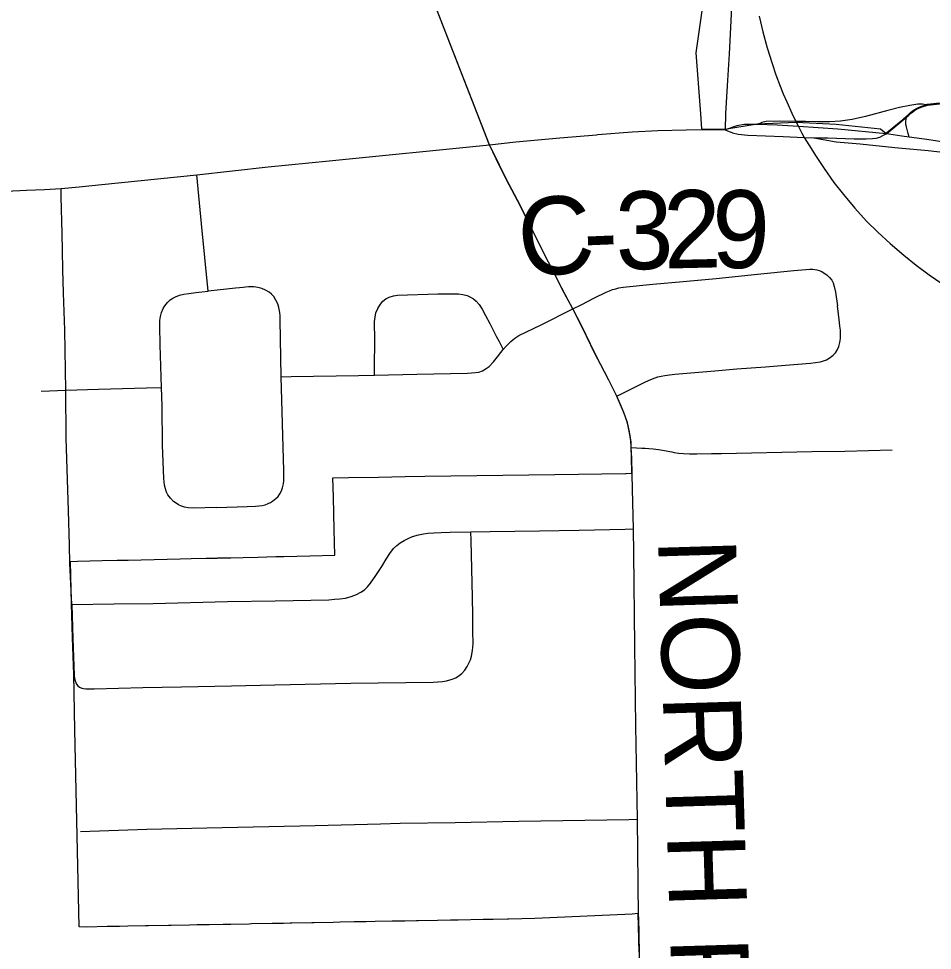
# Model space of a CAD drawing. Extents: x -6.4 to 34, y -4.2 to 22.
# Drawn here: x 3.822 to 4.489, y 17.606 to 18.286 of the extents above; entities that cross this region are included whole.
import ezdxf

# ---------------------------------------------------------------- set-up
doc = ezdxf.new("R2010")
doc.units = 0
for name, color, linetype in [('GM_X_City_Street', 7, 'Continuous'), ('GM_X_Corporation', 7, 'Continuous'), ('GM_X_County_Road', 7, 'Continuous'), ('GM_X_County_Road_Text', 7, 'Continuous'), ('GM_X_Interchange_Ramps', 7, 'Continuous'), ('GM_X_State_Route', 7, 'Continuous'), ('GM_X_Township_Road', 7, 'Continuous')]:
    doc.layers.add(name, color=color, linetype=linetype)

msp = doc.modelspace()

# ---------------------------------------------------------------- linework, layer by layer
at = {"layer": 'GM_X_City_Street'}
for points in [[(3.96669, 17.92881), (3.94956, 17.92831), (3.94597, 17.92852), (3.94309, 17.92911), (3.9409, 17.92989), (3.93872, 17.93082), (3.93703, 17.93198), (3.93517, 17.93332), (3.93286, 17.93563), (3.93114, 17.9381), (3.93008, 17.94016), (3.9293, 17.94237), (3.9285, 17.94515), (3.92824, 17.94764), (3.92798, 17.95007), (3.92719, 17.97433), (3.9268, 18.00298), (3.92636, 18.01641), (3.92534, 18.04756), (3.92515, 18.06117), (3.92525, 18.06541), (3.92571, 18.06838), (3.9265, 18.07126), (3.92766, 18.074), (3.92884, 18.07604), (3.93066, 18.07839), (3.93281, 18.08043), (3.93473, 18.08176), (3.93669, 18.08267), (3.93954, 18.08374), (3.94274, 18.08454), (3.9463, 18.08507), (3.95155, 18.08575), (3.96047, 18.0868), (3.95567, 18.13599), (3.95218, 18.1718)], [(3.86092, 17.85807), (3.8596, 17.88825), (3.85921, 17.90128), (3.85845, 17.92672), (3.85694, 17.97949), (3.85673, 18.01448), (3.85577, 18.05828), (3.85481, 18.08548), (3.85445, 18.10223), (3.85429, 18.11649), (3.85398, 18.12892), (3.85333, 18.15554), (3.85316, 18.16181)], [(3.96669, 17.92881), (3.98887, 17.9295), (3.99504, 17.92972), (3.99983, 17.93022), (4.00212, 17.9308), (4.00427, 17.93173), (4.0058, 17.93246), (4.00737, 17.93351), (4.00973, 17.93534), (4.01139, 17.93699), (4.01278, 17.93888), (4.01389, 17.94095), (4.01471, 17.94316), (4.01533, 17.94605), (4.01552, 17.94831), (4.01568, 17.95025), (4.01567, 17.95292), (4.01566, 17.95575), (4.01358, 18.02423), (4.01305, 18.0658), (4.01287, 18.06874), (4.01272, 18.07124), (4.01204, 18.07477), (4.01119, 18.07764), (4.00991, 18.08029), (4.00826, 18.08279), (4.00672, 18.08455), (4.00491, 18.08601), (4.00238, 18.08751), (3.99962, 18.08863), (3.99673, 18.08941), (3.99377, 18.08982), (3.99185, 18.09002), (3.98981, 18.08994), (3.98776, 18.08976), (3.98592, 18.08957), (3.98329, 18.08927), (3.98038, 18.08894), (3.96047, 18.0868)], [(4.08186, 18.02551), (4.08189, 18.03146), (4.08199, 18.05072), (4.08184, 18.06469), (4.08225, 18.06789), (4.08286, 18.07101), (4.08417, 18.0742), (4.08614, 18.07731), (4.08784, 18.07937), (4.0901, 18.08124), (4.09244, 18.08246), (4.09564, 18.0834), (4.09855, 18.08377), (4.12807, 18.08479), (4.13682, 18.08492), (4.14026, 18.08487), (4.14309, 18.08482), (4.14629, 18.08445), (4.14942, 18.08359), (4.1518, 18.08251), (4.15402, 18.08111), (4.156, 18.07939), (4.15812, 18.07694), (4.16021, 18.07371), (4.16273, 18.069), (4.1658, 18.06327), (4.16814, 18.05869), (4.17061, 18.05388), (4.17264, 18.04999), (4.17569, 18.04414)], [(4.01358, 18.02423), (4.02099, 18.02437), (4.07009, 18.02528), (4.08186, 18.02551), (4.11269, 18.02609), (4.14971, 18.027), (4.15541, 18.02731), (4.158, 18.02776), (4.16048, 18.02865), (4.16335, 18.03022), (4.16542, 18.03185), (4.1685, 18.0351), (4.17145, 18.03889), (4.17384, 18.04197), (4.17569, 18.04414), (4.17785, 18.04666), (4.17948, 18.04833), (4.18126, 18.05015), (4.18259, 18.05133), (4.18407, 18.05242), (4.18549, 18.05343), (4.18713, 18.05438), (4.20327, 18.06228), (4.22634, 18.07376)], [(3.83863, 18.01387), (3.85673, 18.01448), (3.88046, 18.01529), (3.91556, 18.01615), (3.92636, 18.01641)]]:
    msp.add_lwpolyline(points, dxfattribs=at)
at = {"layer": 'GM_X_Corporation'}
for points in [[(4.32282, 18.30701), (4.31607, 18.26071), (4.31952, 18.21626), (4.32042, 18.20533), (4.33727, 18.20509), (4.36096, 18.20893), (4.38948, 18.21011), (4.41864, 18.2086), (4.45099, 18.20522), (4.45476, 18.20215), (4.45682, 18.20367), (4.46706, 18.21211), (4.46957, 18.21426), (4.47124, 18.21585), (4.47248, 18.21702), (4.47415, 18.21836), (4.47549, 18.21923), (4.47702, 18.22017), (4.47859, 18.22091), (4.48032, 18.22169), (4.48506, 18.22318), (4.49382, 18.22417)], [(4.27477, 17.60429), (4.2742, 17.63243), (4.26978, 17.63193), (4.19881, 17.62872), (4.17986, 17.62838), (4.1789, 17.62836), (4.1684, 17.62818), (4.16092, 17.62805), (4.14283, 17.62772), (4.13724, 17.62762), (4.12767, 17.62744), (4.11355, 17.62717), (4.11252, 17.62715), (4.10395, 17.62699), (4.09736, 17.62686), (4.09461, 17.62681), (4.0822, 17.62657), (4.07566, 17.62644), (4.06704, 17.62628), (4.05672, 17.62608), (4.05173, 17.62599), (4.03777, 17.62572), (4.03594, 17.62568), (4.02141, 17.62541), (4.02014, 17.62538), (4.0154, 17.6253), (4.01067, 17.6252), (4.0072, 17.62513), (3.99204, 17.62484), (3.99041, 17.62481), (3.97689, 17.62455), (3.97146, 17.62445), (3.96119, 17.62425), (3.95251, 17.62409), (3.94673, 17.62398), (3.93357, 17.62373), (3.93153, 17.62369), (3.91696, 17.62341), (3.91462, 17.62337), (3.90181, 17.62315), (3.89568, 17.62304), (3.88665, 17.62288), (3.87195, 17.62261), (3.86645, 17.62276), (3.86306, 17.76652), (3.8624, 17.80712), (3.86144, 17.83361), (3.86072, 17.85862), (3.86012, 17.88933), (3.86512, 17.88964), (3.88311, 17.89006), (3.89408, 17.89031), (3.90205, 17.89049), (3.921, 17.89093), (3.93994, 17.89137), (3.94797, 17.89155), (3.95889, 17.8918), (3.96691, 17.89199), (3.96752, 17.892), (3.97699, 17.89222), (3.98585, 17.89242), (3.99677, 17.89268), (4.00991, 17.89298), (4.01572, 17.89311), (4.03466, 17.89355), (4.05277, 17.89396), (4.05234, 17.91246), (4.05179, 17.93629), (4.05145, 17.95061), (4.06282, 17.95078), (4.08465, 17.9511), (4.10417, 17.95139), (4.11854, 17.95161), (4.13748, 17.95189), (4.15643, 17.95217), (4.17538, 17.95245), (4.19433, 17.95273), (4.2133, 17.95302), (4.26477, 17.95378), (4.26541, 17.95379), (4.26957, 17.95382), (4.26918, 17.96553), (4.26891, 17.97324), (4.26869, 17.97746), (4.26805, 17.98183), (4.26765, 17.98457), (4.26679, 17.98812), (4.26602, 17.99133), (4.26462, 17.99544), (4.26352, 17.99867), (4.25829, 18.01065), (4.25247, 18.02226), (4.24669, 18.03356), (4.24226, 18.04193), (4.23332, 18.06064), (4.22614, 18.07431), (4.22311, 18.08016), (4.21843, 18.08885), (4.21332, 18.09892), (4.20392, 18.11745), (4.188, 18.14945), (4.17985, 18.16501), (4.17286, 18.1787), (4.16541, 18.19414), (4.12649, 18.29417)]]:
    msp.add_lwpolyline(points, dxfattribs=at)
at = {"layer": 'GM_X_County_Road'}
for p, q in [((4.16561, 18.19358), (4.12693, 18.29291)), ((4.32062, 18.20478), (4.33747, 18.20453))]:
    msp.add_line(p, q, dxfattribs=at)
for points in [[(4.40224, 18.19873), (4.41241, 18.19868), (4.43171, 18.19804), (4.43655, 18.19794), (4.44042, 18.19786), (4.44515, 18.19814), (4.44777, 18.19858), (4.45028, 18.19921), (4.45262, 18.20031), (4.45496, 18.20159), (4.45701, 18.20312), (4.46725, 18.21155), (4.46977, 18.21371), (4.47144, 18.21529), (4.47268, 18.21647), (4.47435, 18.2178), (4.47569, 18.21868), (4.47722, 18.21962), (4.47879, 18.22036), (4.48052, 18.22113), (4.48526, 18.22262)], [(4.48526, 18.22262), (4.49402, 18.22362), (4.49803, 18.22402)], [(4.16561, 18.19358), (4.18486, 18.19576), (4.21708, 18.19866), (4.24375, 18.20101), (4.24476, 18.20109)], [(4.24476, 18.20109), (4.26985, 18.20298), (4.28853, 18.204), (4.30911, 18.20464), (4.32062, 18.20478)], [(4.33747, 18.20453), (4.34283, 18.20244), (4.34709, 18.20129), (4.35417, 18.20062), (4.37995, 18.19958), (4.3953, 18.19906), (4.40224, 18.19873)], [(3.62338, 18.15347), (3.70253, 18.15593), (3.81313, 18.15977), (3.82782, 18.16041), (3.84103, 18.16094), (3.85316, 18.16181), (3.86646, 18.16302), (3.88297, 18.16469), (3.95218, 18.1718), (4.00423, 18.17746), (4.04871, 18.18188), (4.16561, 18.19358)], [(4.26976, 17.95327), (4.26938, 17.96498), (4.26911, 17.97268), (4.26889, 17.9769), (4.26825, 17.98128), (4.26784, 17.98401), (4.26699, 17.98756), (4.26622, 17.99077), (4.26482, 17.99489), (4.26372, 17.99812), (4.26104, 18.00446), (4.25849, 18.0101), (4.25267, 18.0217), (4.24689, 18.03301), (4.24246, 18.04138), (4.23352, 18.06009), (4.22634, 18.07376), (4.2233, 18.07961), (4.21863, 18.0883), (4.21352, 18.09837), (4.20412, 18.1169), (4.1882, 18.1489), (4.18004, 18.16446), (4.17306, 18.17815), (4.16561, 18.19358)], [(4.27449, 17.62971), (4.27447, 17.63071), (4.27355, 17.70129), (4.27249, 17.7695), (4.27163, 17.82782), (4.27101, 17.89549), (4.27062, 17.91324), (4.26998, 17.94212), (4.26976, 17.95327)], [(4.27569, 17.54832), (4.27497, 17.60374), (4.27449, 17.62971)]]:
    msp.add_lwpolyline(points, dxfattribs=at)
at = {"layer": 'GM_X_Interchange_Ramps'}
for points in [[(4.33537, 18.46385), (4.33457, 18.46071), (4.33426, 18.45786), (4.33432, 18.45463), (4.33472, 18.45101), (4.33913, 18.41742), (4.34079, 18.40382), (4.34217, 18.39105), (4.34307, 18.37723), (4.34339, 18.36776), (4.34355, 18.35847), (4.34363, 18.34959), (4.34354, 18.3403), (4.34297, 18.31986), (4.34186, 18.28906), (4.34052, 18.26003), (4.3391, 18.23677), (4.33786, 18.21652), (4.33747, 18.20453)], [(4.48526, 18.22262), (4.48158, 18.22333), (4.47978, 18.22331), (4.47815, 18.22324), (4.47227, 18.22237), (4.46463, 18.22082), (4.45618, 18.21872), (4.43999, 18.21422), (4.43028, 18.21207), (4.42166, 18.21087), (4.41359, 18.21035), (4.40489, 18.21032), (4.39613, 18.21053), (4.39038, 18.21067), (4.38913, 18.21069), (4.37752, 18.21094), (4.36759, 18.21073), (4.36421, 18.20991), (4.36116, 18.20838)], [(4.5049, 18.1944), (4.48467, 18.19754), (4.47172, 18.19926), (4.46655, 18.19994), (4.45685, 18.20132), (4.45496, 18.20159), (4.41986, 18.20505), (4.39099, 18.20702), (4.37551, 18.20795), (4.36116, 18.20838), (4.35171, 18.20844), (4.34612, 18.20746), (4.33747, 18.20453)], [(4.47172, 18.19926), (4.47106, 18.20181), (4.46977, 18.20683), (4.46945, 18.20846), (4.46937, 18.20979), (4.46945, 18.21116), (4.46958, 18.21213), (4.46977, 18.21371)], [(4.40224, 18.19873), (4.40895, 18.19747), (4.41843, 18.19569), (4.43594, 18.19432), (4.46136, 18.19172), (4.48554, 18.18936), (4.49837, 18.18799)]]:
    msp.add_lwpolyline(points, dxfattribs=at)
at = {"layer": 'GM_X_State_Route'}
for points in [[(4.36246, 18.28747), (4.36516, 18.27601), (4.36814, 18.26431), (4.37175, 18.25288), (4.37463, 18.24465), (4.37766, 18.23651), (4.37996, 18.23075), (4.38251, 18.22491), (4.3862, 18.21677), (4.38913, 18.21069), (4.38965, 18.20961)], [(4.38965, 18.20961), (4.39099, 18.20702), (4.39351, 18.20204), (4.3953, 18.19906), (4.39861, 18.19356), (4.40388, 18.18501), (4.4098, 18.17636), (4.41695, 18.16612), (4.42385, 18.15736), (4.43212, 18.14727), (4.44072, 18.13791), (4.44882, 18.12987), (4.45791, 18.12145), (4.46778, 18.11296), (4.477, 18.10564), (4.4865, 18.09867), (4.49573, 18.09243)]]:
    msp.add_lwpolyline(points, dxfattribs=at)
at = {"layer": 'GM_X_Township_Road'}
for points in [[(4.22634, 18.07376), (4.23244, 18.07689), (4.24226, 18.08188), (4.25071, 18.08595), (4.25324, 18.08706), (4.25546, 18.08792), (4.2577, 18.08858), (4.26002, 18.08914), (4.26326, 18.08964), (4.28481, 18.09183), (4.30703, 18.09395), (4.33107, 18.09606), (4.36119, 18.0992), (4.38761, 18.1018), (4.39928, 18.10275), (4.40159, 18.10278), (4.4045, 18.10235), (4.40611, 18.10189), (4.40798, 18.10112), (4.40987, 18.09992), (4.41161, 18.09861), (4.41377, 18.09671), (4.41528, 18.09491), (4.4164, 18.09283), (4.41717, 18.09009), (4.41794, 18.08615), (4.41948, 18.07617)], [(4.25849, 18.0101), (4.26538, 18.01353), (4.27887, 18.02025), (4.28174, 18.02156), (4.28447, 18.02279), (4.28645, 18.02354), (4.28846, 18.0243), (4.29095, 18.0248), (4.2935, 18.02532), (4.297, 18.02573), (4.30079, 18.02618), (4.32994, 18.02873), (4.34609, 18.03004), (4.3671, 18.03165), (4.38439, 18.03296), (4.39983, 18.03416), (4.40711, 18.0352), (4.40939, 18.0358), (4.41154, 18.03672), (4.41408, 18.03825), (4.41535, 18.03926), (4.41641, 18.0401), (4.41801, 18.04181), (4.41925, 18.04374), (4.42047, 18.04646), (4.42132, 18.04931), (4.42173, 18.05224), (4.42176, 18.05404), (4.42179, 18.05586), (4.42158, 18.05833), (4.42132, 18.06119), (4.42109, 18.06383), (4.41948, 18.07617)], [(4.26911, 17.97268), (4.27675, 17.97224), (4.2792, 17.97209), (4.28195, 17.97193), (4.28508, 17.97159), (4.28883, 17.97118), (4.29175, 17.97065), (4.29871, 17.96938), (4.30045, 17.96906), (4.30349, 17.96863), (4.30707, 17.96836), (4.31147, 17.96804), (4.31701, 17.96794), (4.32754, 17.9682), (4.33501, 17.96828), (4.40074, 17.96966), (4.42496, 17.97009), (4.45951, 17.97083)], [(3.86092, 17.85807), (3.89187, 17.85846), (3.92039, 17.85889), (3.9746, 17.86025), (4.00938, 17.86068), (4.04849, 17.8615), (4.05271, 17.86185), (4.05648, 17.86215), (4.0607, 17.86279), (4.06481, 17.86385), (4.06874, 17.8654), (4.07191, 17.86711), (4.07436, 17.86883), (4.07656, 17.87085), (4.07892, 17.87361), (4.08286, 17.87911), (4.08713, 17.88584), (4.09039, 17.89106), (4.09303, 17.89529), (4.09574, 17.89884), (4.098, 17.90115), (4.1006, 17.9031), (4.10347, 17.90487), (4.10629, 17.90633), (4.10961, 17.9077), (4.11385, 17.90899), (4.11761, 17.90965), (4.12065, 17.91004), (4.12505, 17.91041), (4.13038, 17.91065), (4.13685, 17.91095), (4.15215, 17.91118), (4.16606, 17.91138), (4.20205, 17.91182), (4.23115, 17.91226), (4.2647, 17.91309), (4.27062, 17.91324)], [(3.8626, 17.80656), (3.86295, 17.80393), (3.86345, 17.80237), (3.86395, 17.80102), (3.86451, 17.79988), (3.86536, 17.79868), (3.86658, 17.79768), (3.86823, 17.79687), (3.86954, 17.79667), (3.87115, 17.79655), (3.87319, 17.79654), (3.87721, 17.79652), (3.91268, 17.79738), (3.94099, 17.79792), (3.9775, 17.79878), (4.00905, 17.7994), (4.0644, 17.80066), (4.12467, 17.80147), (4.13137, 17.80176), (4.13431, 17.80227), (4.13838, 17.80344), (4.14113, 17.80457), (4.1436, 17.8061), (4.14536, 17.80764), (4.14766, 17.81023), (4.14927, 17.81271), (4.15044, 17.81484), (4.15171, 17.81754), (4.15259, 17.82036), (4.15329, 17.82452), (4.15363, 17.82938), (4.15352, 17.83864), (4.15348, 17.85003), (4.15319, 17.86342), (4.15229, 17.90466), (4.15215, 17.91118)], [(3.86092, 17.85807), (3.86164, 17.83305), (3.8626, 17.80656)], [(3.86743, 17.69246), (3.91573, 17.69411), (3.9595, 17.69503), (4.03846, 17.69664), (4.08605, 17.69803), (4.10047, 17.69837), (4.14057, 17.6989), (4.18715, 17.69982), (4.26718, 17.70118), (4.27355, 17.70129)]]:
    msp.add_lwpolyline(points, dxfattribs=at)

# ---------------------------------------------------------------- texts
at = {"layer": 'GM_X_County_Road_Text'}
for s, height, rotation, p in [('3', 0.05682, 1.46513, (4.25809, 18.10235)), ('2', 0.05682, 1.30113, (4.29304, 18.10325)), ('9', 0.05682, 358.87328, (4.32739, 18.10404)), ('C', 0.05682, 7.07467, (4.18994, 18.09575)), ('-', 0.05682, 2.3775, (4.23502, 18.10139)), ('NORTH RD', 0.056818, 271.7471, (4.28859, 17.90567))]:
    msp.add_text(s, height=height, rotation=rotation, dxfattribs=at).set_placement(p)

doc.saveas('drawing.dxf')
